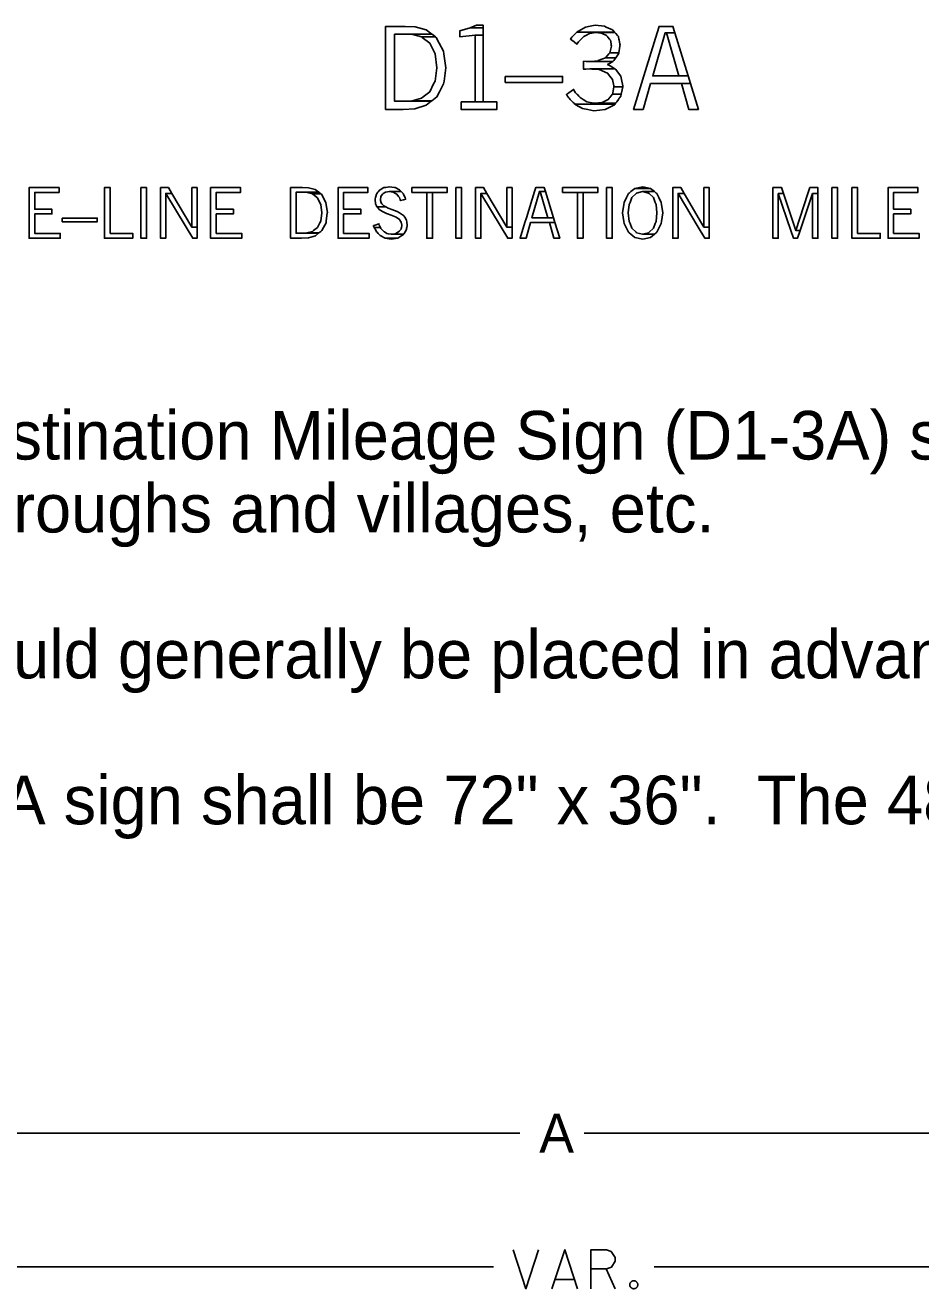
# Model space of a CAD drawing. Extents: x 0.011 to 0.188, y 0.004 to 0.261.
# Drawn here: x 0.0822 to 0.1286, y 0.1954 to 0.2609 of the extents above; entities that cross this region are included whole.
import ezdxf

# ---------------------------------------------------------------- set-up
doc = ezdxf.new("R2010")
doc.units = 0
doc.layers.add('1', color=7, linetype='Continuous')
doc.layers.add('3', color=7, linetype='Continuous')

msp = doc.modelspace()

# ---------------------------------------------------------------- linework, layer by layer
at = {"layer": '1'}
for points in [[(0.100861, 0.256562), (0.100861, 0.256526), (0.101776, 0.256526), (0.10237, 0.256562), (0.102964, 0.256741), (0.103229, 0.256947), (0.101328, 0.256947), (0.101328, 0.256972), (0.101328, 0.257102), (0.101328, 0.257171), (0.101328, 0.257439), (0.101328, 0.257841), (0.101328, 0.257985), (0.101328, 0.258672), (0.101328, 0.258675), (0.101328, 0.259396), (0.101328, 0.259539), (0.101328, 0.25995), (0.101328, 0.260253), (0.101328, 0.260283), (0.101328, 0.260403), (0.101328, 0.260422), (0.103257, 0.260422), (0.102956, 0.26065), (0.102393, 0.260797), (0.101881, 0.260822), (0.100861, 0.260822), (0.100861, 0.260797), (0.100861, 0.26065), (0.100861, 0.260422), (0.100861, 0.260403), (0.100861, 0.260283), (0.100861, 0.260253), (0.100861, 0.25995), (0.100861, 0.259539), (0.100861, 0.259396), (0.100861, 0.258675), (0.100861, 0.258672), (0.100861, 0.257985), (0.100861, 0.257841), (0.100861, 0.257439), (0.100861, 0.257171), (0.100861, 0.257102), (0.100861, 0.256972), (0.100861, 0.256947), (0.100861, 0.256741)], [(0.1047, 0.260379), (0.1047, 0.26029), (0.105496, 0.260379), (0.105922, 0.260379), (0.105922, 0.260588), (0.105922, 0.260753), (0.105244, 0.260753), (0.1047, 0.260588)], [(0.105575, 0.260884), (0.105244, 0.260753), (0.105922, 0.260753), (0.105922, 0.260884)], [(0.110984, 0.260653), (0.110775, 0.26053), (0.11272, 0.26053), (0.112616, 0.260653), (0.112298, 0.260794), (0.112206, 0.260836), (0.111724, 0.260884), (0.111723, 0.260884), (0.111456, 0.260836), (0.111226, 0.260794)], [(0.114117, 0.257862), (0.113706, 0.256526), (0.114206, 0.256526), (0.11459, 0.257862), (0.116661, 0.257862), (0.116538, 0.258261), (0.114704, 0.258261), (0.115347, 0.260499), (0.115849, 0.260499), (0.11575, 0.260822), (0.115028, 0.260822), (0.114929, 0.260499), (0.114239, 0.258261)], [(0.102266, 0.260403), (0.102716, 0.260283), (0.10344, 0.260283), (0.103282, 0.260403), (0.103257, 0.260422), (0.101775, 0.260422)], [(0.102727, 0.257102), (0.102228, 0.256972), (0.103261, 0.256972), (0.103429, 0.257102), (0.103518, 0.257171), (0.103658, 0.257439), (0.103868, 0.257841), (0.103888, 0.257985), (0.103979, 0.258672), (0.10398, 0.258675), (0.103877, 0.259396), (0.103857, 0.259539), (0.10364, 0.25995), (0.103481, 0.260253), (0.10344, 0.260283), (0.102716, 0.260283), (0.102756, 0.260253), (0.103148, 0.25995), (0.103351, 0.259539), (0.103422, 0.259396), (0.10351, 0.258675), (0.103511, 0.258672), (0.10342, 0.257985), (0.103349, 0.257841), (0.103151, 0.257439), (0.102813, 0.257171)], [(0.105496, 0.26029), (0.105496, 0.256911), (0.105922, 0.256911), (0.105922, 0.26029), (0.105922, 0.260379), (0.105496, 0.260379)], [(0.110635, 0.260018), (0.110777, 0.259912), (0.110855, 0.260018), (0.110945, 0.260111), (0.111, 0.260168), (0.1111, 0.260271), (0.111111, 0.260282), (0.11114, 0.260298), (0.111231, 0.260348), (0.11123, 0.260348), (0.111421, 0.260452), (0.111552, 0.260473), (0.111736, 0.260502), (0.112745, 0.260502), (0.11272, 0.26053), (0.110775, 0.26053), (0.110746, 0.260502), (0.110717, 0.260473), (0.110696, 0.260452), (0.110591, 0.260348), (0.11054, 0.260298), (0.110524, 0.260282), (0.110513, 0.260271), (0.110436, 0.260168), (0.110511, 0.260111)], [(0.112564, 0.259795), (0.112483, 0.259462), (0.112946, 0.259462), (0.113006, 0.259795), (0.113016, 0.259846), (0.113001, 0.259912), (0.112979, 0.260018), (0.112959, 0.260111), (0.112947, 0.260168), (0.112925, 0.260271), (0.112923, 0.260282), (0.11292, 0.260298), (0.112877, 0.260348), (0.112788, 0.260452), (0.11277, 0.260473), (0.112745, 0.260502), (0.111736, 0.260502), (0.112032, 0.260473), (0.112078, 0.260452), (0.112312, 0.260348), (0.112353, 0.260298), (0.112366, 0.260282), (0.112376, 0.260271), (0.112461, 0.260168), (0.112509, 0.260111), (0.112524, 0.260018), (0.112543, 0.259912), (0.112555, 0.259846)], [(0.115412, 0.260499), (0.116054, 0.258261), (0.116538, 0.258261), (0.115849, 0.260499)], [(0.11243, 0.259402), (0.112256, 0.259201), (0.112795, 0.259201), (0.112936, 0.259402), (0.112946, 0.259462), (0.112482, 0.259462)], [(0.11112, 0.25861), (0.11112, 0.258609), (0.111142, 0.25861), (0.111229, 0.258616), (0.11145, 0.258624), (0.112744, 0.258624), (0.112494, 0.258786), (0.112359, 0.258844), (0.11247, 0.258896), (0.112629, 0.259007), (0.111443, 0.259007), (0.111259, 0.259013), (0.11112, 0.259021), (0.11112, 0.259013), (0.11112, 0.259007), (0.11112, 0.258896), (0.11112, 0.258844), (0.11112, 0.258786), (0.11112, 0.258624), (0.11112, 0.258616)], [(0.111512, 0.259013), (0.111443, 0.259007), (0.112629, 0.259007), (0.112637, 0.259013), (0.112676, 0.25904), (0.11269, 0.25905), (0.112795, 0.259201), (0.112255, 0.259201), (0.111882, 0.25905), (0.111859, 0.25904)], [(0.112683, 0.257744), (0.112692, 0.2577), (0.113146, 0.2577), (0.113155, 0.257744), (0.113086, 0.258073), (0.113049, 0.258251), (0.112933, 0.258397), (0.112786, 0.258584), (0.112786, 0.258584), (0.112766, 0.258609), (0.112766, 0.25861), (0.112757, 0.258616), (0.112744, 0.258624), (0.11145, 0.258624), (0.111549, 0.258616), (0.111614, 0.25861), (0.11163, 0.258609), (0.111926, 0.258584), (0.112364, 0.258397), (0.112481, 0.258251), (0.112624, 0.258073)], [(0.10706, 0.258234), (0.10706, 0.257924), (0.110029, 0.257924), (0.110029, 0.258234)], [(0.110626, 0.256841), (0.11067, 0.256799), (0.11275, 0.256799), (0.112781, 0.256841), (0.111684, 0.256841), (0.111456, 0.256885), (0.111294, 0.256917), (0.111095, 0.257038), (0.110996, 0.257098), (0.110938, 0.257134), (0.110865, 0.257214), (0.11078, 0.257309), (0.11077, 0.25732), (0.110707, 0.25739), (0.110599, 0.257563), (0.110347, 0.25739), (0.110245, 0.25732), (0.11023, 0.257309), (0.110291, 0.257214), (0.110342, 0.257134), (0.110366, 0.257098), (0.110427, 0.257038), (0.110549, 0.256917), (0.110582, 0.256885)], [(0.112077, 0.256885), (0.111684, 0.256841), (0.112781, 0.256841), (0.112813, 0.256885), (0.112837, 0.256917), (0.112925, 0.257038), (0.112969, 0.257098), (0.112996, 0.257134), (0.112995, 0.257134), (0.113054, 0.257214), (0.113072, 0.257309), (0.113074, 0.25732), (0.112621, 0.25732), (0.112612, 0.257309), (0.112538, 0.257214), (0.112475, 0.257134), (0.112448, 0.257098), (0.1124, 0.257038), (0.112144, 0.256917)], [(0.112634, 0.25739), (0.112621, 0.25732), (0.113074, 0.25732), (0.113087, 0.25739), (0.113146, 0.2577), (0.112691, 0.2577)], [(0.116187, 0.257862), (0.116572, 0.256526), (0.117072, 0.256526), (0.116661, 0.257862)], [(0.102228, 0.256972), (0.101709, 0.256947), (0.103229, 0.256947), (0.103261, 0.256972)], [(0.104773, 0.256911), (0.104773, 0.256526), (0.106626, 0.256526), (0.106626, 0.256911)], [(0.111344, 0.256514), (0.111645, 0.256456), (0.112237, 0.256514), (0.11234, 0.256568), (0.112726, 0.256766), (0.11275, 0.256799), (0.110669, 0.256799), (0.110726, 0.256766), (0.111065, 0.256568)], [(0.082388, 0.2501), (0.082388, 0.249848), (0.083998, 0.249848), (0.083998, 0.2501), (0.082676, 0.2501), (0.082676, 0.251105), (0.083569, 0.251105), (0.083569, 0.251349), (0.082676, 0.251349), (0.082676, 0.252226), (0.083936, 0.252226), (0.083936, 0.252474), (0.082388, 0.252474), (0.082388, 0.252226), (0.082388, 0.251349), (0.082388, 0.251105)], [(0.08629, 0.2501), (0.08629, 0.249848), (0.08776, 0.249848), (0.08776, 0.2501), (0.086587, 0.2501), (0.086587, 0.252474), (0.08629, 0.252474)], [(0.088181, 0.252474), (0.088181, 0.249848), (0.088475, 0.249848), (0.088475, 0.252474)], [(0.089197, 0.250424), (0.089197, 0.249848), (0.08947, 0.249848), (0.08947, 0.250424), (0.08947, 0.252171), (0.089786, 0.252171), (0.089609, 0.252474), (0.089197, 0.252474), (0.089197, 0.252171)], [(0.090517, 0.250424), (0.090862, 0.249848), (0.091087, 0.249848), (0.091087, 0.250424), (0.090814, 0.250424), (0.089786, 0.252171), (0.08947, 0.252171)], [(0.090814, 0.252474), (0.090814, 0.250424), (0.091087, 0.250424), (0.091087, 0.252474)], [(0.091793, 0.2501), (0.091793, 0.249848), (0.093402, 0.249848), (0.093402, 0.2501), (0.092081, 0.2501), (0.092081, 0.251105), (0.092974, 0.251105), (0.092974, 0.251349), (0.092081, 0.251349), (0.092081, 0.252226), (0.093341, 0.252226), (0.093341, 0.252474), (0.091793, 0.252474), (0.091793, 0.252226), (0.091793, 0.251349), (0.091793, 0.251105)], [(0.095934, 0.24987), (0.095934, 0.249848), (0.096494, 0.249848), (0.096857, 0.24987), (0.09722, 0.249979), (0.097382, 0.250106), (0.09622, 0.250106), (0.09622, 0.250121), (0.09622, 0.2502), (0.09622, 0.250242), (0.09622, 0.250406), (0.09622, 0.250652), (0.09622, 0.25074), (0.09622, 0.25116), (0.09622, 0.251161), (0.09622, 0.251603), (0.09622, 0.25169), (0.09622, 0.251941), (0.09622, 0.252126), (0.09622, 0.252144), (0.09622, 0.252217), (0.09622, 0.252229), (0.097399, 0.252229), (0.097215, 0.252369), (0.096871, 0.252459), (0.096558, 0.252474), (0.095934, 0.252474), (0.095934, 0.252459), (0.095934, 0.252369), (0.095934, 0.252229), (0.095934, 0.252217), (0.095934, 0.252144), (0.095934, 0.252126), (0.095934, 0.251941), (0.095934, 0.25169), (0.095934, 0.251603), (0.095934, 0.251161), (0.095934, 0.25116), (0.095934, 0.25074), (0.095934, 0.250652), (0.095934, 0.250406), (0.095934, 0.250242), (0.095934, 0.2502), (0.095934, 0.250121), (0.095934, 0.250106), (0.095934, 0.249979)], [(0.096793, 0.252217), (0.097069, 0.252144), (0.097511, 0.252144), (0.097414, 0.252217), (0.097399, 0.252229), (0.096493, 0.252229)], [(0.097075, 0.2502), (0.09677, 0.250121), (0.097401, 0.250121), (0.097504, 0.2502), (0.097558, 0.250242), (0.097644, 0.250406), (0.097772, 0.250652), (0.097784, 0.25074), (0.09784, 0.25116), (0.097841, 0.251161), (0.097778, 0.251603), (0.097766, 0.25169), (0.097633, 0.251941), (0.097536, 0.252126), (0.097511, 0.252144), (0.097068, 0.252144), (0.097092, 0.252126), (0.097332, 0.251941), (0.097456, 0.25169), (0.097499, 0.251603), (0.097554, 0.251161), (0.097554, 0.25116), (0.097499, 0.25074), (0.097455, 0.250652), (0.097334, 0.250406), (0.097128, 0.250242)], [(0.098396, 0.2501), (0.098396, 0.249848), (0.100005, 0.249848), (0.100005, 0.2501), (0.098684, 0.2501), (0.098684, 0.251105), (0.099577, 0.251105), (0.099577, 0.251349), (0.098684, 0.251349), (0.098684, 0.252226), (0.099944, 0.252226), (0.099944, 0.252474), (0.098396, 0.252474), (0.098396, 0.252226), (0.098396, 0.251349), (0.098396, 0.251105)], [(0.100385, 0.251524), (0.100409, 0.251469), (0.100866, 0.251469), (0.10076, 0.251524), (0.100662, 0.251639), (0.100626, 0.251682), (0.100601, 0.251798), (0.100591, 0.251844), (0.100596, 0.251875), (0.1006, 0.251898), (0.100609, 0.251954), (0.10061, 0.25196), (0.10062, 0.252013), (0.100696, 0.252129), (0.100709, 0.252149), (0.100722, 0.252157), (0.100739, 0.252168), (0.10086, 0.252242), (0.100863, 0.252243), (0.10105, 0.252273), (0.101665, 0.252273), (0.101601, 0.252341), (0.101579, 0.252364), (0.101358, 0.252469), (0.101323, 0.252486), (0.101044, 0.252516), (0.101043, 0.252516), (0.100871, 0.252486), (0.100772, 0.252469), (0.100583, 0.252364), (0.100541, 0.252341), (0.100486, 0.252273), (0.100462, 0.252243), (0.10046, 0.252242), (0.1004, 0.252168), (0.100391, 0.252157), (0.100388, 0.252149), (0.100383, 0.252129), (0.100348, 0.252013), (0.100333, 0.25196), (0.100331, 0.251954), (0.100315, 0.251898), (0.100316, 0.251875), (0.100318, 0.251844), (0.100321, 0.251798), (0.100329, 0.251682), (0.100332, 0.251639)], [(0.101622, 0.251844), (0.101639, 0.251798), (0.101794, 0.251844), (0.101901, 0.251875), (0.101893, 0.251898), (0.101876, 0.251954), (0.101874, 0.25196), (0.101846, 0.252013), (0.101785, 0.252129), (0.101774, 0.252149), (0.10177, 0.252157), (0.101765, 0.252168), (0.101694, 0.252242), (0.101693, 0.252243), (0.101665, 0.252273), (0.10105, 0.252273), (0.101239, 0.252243), (0.10125, 0.252242), (0.101381, 0.252168), (0.1014, 0.252157), (0.101414, 0.252149), (0.10145, 0.252129), (0.101535, 0.252013), (0.101575, 0.25196), (0.10158, 0.251954), (0.101601, 0.251898), (0.10161, 0.251875)], [(0.102227, 0.252474), (0.102227, 0.252222), (0.104056, 0.252222), (0.104056, 0.252474)], [(0.102993, 0.252222), (0.102993, 0.249848), (0.10329, 0.249848), (0.10329, 0.252222)], [(0.104507, 0.252474), (0.104507, 0.249848), (0.104801, 0.249848), (0.104801, 0.252474)], [(0.105524, 0.250424), (0.105524, 0.249848), (0.105797, 0.249848), (0.105797, 0.250424), (0.105797, 0.252171), (0.106113, 0.252171), (0.105936, 0.252474), (0.105524, 0.252474), (0.105524, 0.252171)], [(0.106844, 0.250424), (0.107189, 0.249848), (0.107414, 0.249848), (0.107414, 0.250424), (0.107141, 0.250424), (0.106113, 0.252171), (0.105797, 0.252171)], [(0.107141, 0.252474), (0.107141, 0.250424), (0.107414, 0.250424), (0.107414, 0.252474)], [(0.108081, 0.250665), (0.10783, 0.249848), (0.108136, 0.249848), (0.10837, 0.250665), (0.109636, 0.250665), (0.109561, 0.250909), (0.10844, 0.250909), (0.108833, 0.252276), (0.10914, 0.252276), (0.109079, 0.252474), (0.108638, 0.252474), (0.108577, 0.252276), (0.108156, 0.250909)], [(0.108872, 0.252276), (0.109265, 0.250909), (0.109561, 0.250909), (0.10914, 0.252276)], [(0.110032, 0.252474), (0.110032, 0.252222), (0.111861, 0.252222), (0.111861, 0.252474)], [(0.110797, 0.252222), (0.110797, 0.249848), (0.111094, 0.249848), (0.111094, 0.252222)], [(0.112312, 0.252474), (0.112312, 0.249848), (0.112606, 0.249848), (0.112606, 0.252474)], [(0.113773, 0.24989), (0.114181, 0.249806), (0.114589, 0.24989), (0.114797, 0.250058), (0.11418, 0.250058), (0.11387, 0.250129), (0.113838, 0.250159), (0.113626, 0.250362), (0.113527, 0.250613), (0.113484, 0.250724), (0.113437, 0.251161), (0.113484, 0.251597), (0.113527, 0.251708), (0.113626, 0.25196), (0.113838, 0.252162), (0.11387, 0.252192), (0.11418, 0.252264), (0.114797, 0.252264), (0.114589, 0.252432), (0.113772, 0.252432), (0.113565, 0.252264), (0.113476, 0.252192), (0.113439, 0.252162), (0.113339, 0.25196), (0.113215, 0.251708), (0.1132, 0.251597), (0.113143, 0.251161), (0.1132, 0.250724), (0.113215, 0.250613), (0.113339, 0.250362), (0.113439, 0.250159), (0.113476, 0.250129), (0.113565, 0.250058)], [(0.114181, 0.252516), (0.113773, 0.252432), (0.114589, 0.252432)], [(0.11449, 0.250129), (0.11418, 0.250058), (0.114797, 0.250058), (0.114885, 0.250129), (0.114885, 0.250129), (0.114923, 0.250159), (0.115023, 0.250362), (0.115147, 0.250613), (0.115161, 0.250724), (0.115218, 0.251161), (0.115161, 0.251597), (0.115147, 0.251708), (0.115023, 0.25196), (0.114923, 0.252162), (0.114885, 0.252192), (0.114885, 0.252192), (0.114797, 0.252264), (0.11418, 0.252264), (0.11449, 0.252192), (0.114522, 0.252162), (0.114734, 0.25196), (0.114832, 0.251708), (0.114876, 0.251597), (0.114923, 0.251161), (0.114876, 0.250724), (0.114832, 0.250613), (0.114734, 0.250362), (0.114522, 0.250159)], [(0.115739, 0.250424), (0.115739, 0.249848), (0.116012, 0.249848), (0.116012, 0.250424), (0.116012, 0.252171), (0.116329, 0.252171), (0.116151, 0.252474), (0.115739, 0.252474), (0.115739, 0.252171)], [(0.117059, 0.250424), (0.117404, 0.249848), (0.117629, 0.249848), (0.117629, 0.250424), (0.117356, 0.250424), (0.116329, 0.252171), (0.116012, 0.252171)], [(0.117356, 0.252474), (0.117356, 0.250424), (0.117629, 0.250424), (0.117629, 0.252474)], [(0.120931, 0.250255), (0.120931, 0.249848), (0.121211, 0.249848), (0.121211, 0.250255), (0.121211, 0.252159), (0.12148, 0.252159), (0.121376, 0.252474), (0.120931, 0.252474), (0.120931, 0.252159)], [(0.12186, 0.250255), (0.121999, 0.249848), (0.122198, 0.249848), (0.122336, 0.250255), (0.12211, 0.250255), (0.12148, 0.252159), (0.121211, 0.252159)], [(0.122743, 0.252159), (0.12211, 0.250255), (0.122336, 0.250255), (0.122987, 0.252159), (0.123266, 0.252159), (0.123266, 0.252474), (0.122848, 0.252474)], [(0.122987, 0.250255), (0.122987, 0.249848), (0.123266, 0.249848), (0.123266, 0.250255), (0.123266, 0.252159), (0.122987, 0.252159)], [(0.123989, 0.252474), (0.123989, 0.249848), (0.124283, 0.249848), (0.124283, 0.252474)], [(0.125022, 0.2501), (0.125022, 0.249848), (0.126492, 0.249848), (0.126492, 0.2501), (0.125319, 0.2501), (0.125319, 0.252474), (0.125022, 0.252474)], [(0.126895, 0.2501), (0.126895, 0.249848), (0.128505, 0.249848), (0.128505, 0.2501), (0.127184, 0.2501), (0.127184, 0.251105), (0.128077, 0.251105), (0.128077, 0.251349), (0.127184, 0.251349), (0.127184, 0.252226), (0.128444, 0.252226), (0.128444, 0.252474), (0.126895, 0.252474), (0.126895, 0.252226), (0.126895, 0.251349), (0.126895, 0.251105)], [(0.101361, 0.250084), (0.10115, 0.250056), (0.101796, 0.250056), (0.101815, 0.250084), (0.101822, 0.250095), (0.101873, 0.250172), (0.101884, 0.250188), (0.101883, 0.250188), (0.101897, 0.250208), (0.101933, 0.250262), (0.101943, 0.250322), (0.101949, 0.250358), (0.101957, 0.250402), (0.101973, 0.250496), (0.101975, 0.250507), (0.101976, 0.250513), (0.10198, 0.250531), (0.101956, 0.250684), (0.101941, 0.250789), (0.10192, 0.250825), (0.101851, 0.250938), (0.101805, 0.251014), (0.101779, 0.251032), (0.101636, 0.251136), (0.101588, 0.251172), (0.101451, 0.25123), (0.10132, 0.251287), (0.101187, 0.251335), (0.100987, 0.251407), (0.100866, 0.251469), (0.100409, 0.251469), (0.100467, 0.251407), (0.100534, 0.251335), (0.100609, 0.251287), (0.100698, 0.25123), (0.100832, 0.251172), (0.100913, 0.251136), (0.101197, 0.251032), (0.101239, 0.251014), (0.101413, 0.250938), (0.101582, 0.250825), (0.101605, 0.250789), (0.101672, 0.250684), (0.101695, 0.250531), (0.101698, 0.250513), (0.101697, 0.250507), (0.101694, 0.250496), (0.101675, 0.250402), (0.101666, 0.250358), (0.101659, 0.250322), (0.101609, 0.250262), (0.101565, 0.250208), (0.101549, 0.250188), (0.101536, 0.250172), (0.101383, 0.250095)], [(0.084106, 0.250892), (0.084106, 0.250703), (0.085921, 0.250703), (0.085921, 0.250892)], [(0.09677, 0.250121), (0.096453, 0.250106), (0.097382, 0.250106), (0.097401, 0.250121)], [(0.100241, 0.250496), (0.100275, 0.250402), (0.100592, 0.250402), (0.100544, 0.250496), (0.10054, 0.250507), (0.100538, 0.250513), (0.100533, 0.250531), (0.100532, 0.250531), (0.100512, 0.250595), (0.100512, 0.250595), (0.100313, 0.250531), (0.100255, 0.250513), (0.100237, 0.250507)], [(0.10058, 0.249982), (0.100833, 0.249853), (0.101489, 0.249853), (0.101706, 0.249982), (0.101775, 0.250022), (0.101796, 0.250056), (0.10115, 0.250056), (0.100994, 0.250084), (0.100993, 0.250084), (0.100932, 0.250095), (0.100806, 0.250172), (0.10078, 0.250188), (0.100747, 0.250208), (0.1007, 0.250262), (0.100646, 0.250322), (0.100646, 0.250322), (0.100614, 0.250358), (0.100592, 0.250402), (0.100275, 0.250402), (0.100297, 0.250358), (0.100316, 0.250322), (0.100347, 0.250262), (0.100375, 0.250208), (0.100386, 0.250188), (0.100401, 0.250172), (0.100474, 0.250095), (0.100484, 0.250084), (0.10051, 0.250056), (0.100542, 0.250022)], [(0.109346, 0.250665), (0.109581, 0.249848), (0.109887, 0.249848), (0.109636, 0.250665)], [(0.100838, 0.249853), (0.101143, 0.249806), (0.101487, 0.249853), (0.101489, 0.249853), (0.100832, 0.249853)]]:
    msp.add_lwpolyline(points, close=True, dxfattribs=at)
at = {"layer": '3'}
for p, q in [((0.107815, 0.20348), (0.049001, 0.20348)), ((0.111148, 0.20348), (0.169961, 0.20348)), ((0.106457, 0.19655), (0.077855, 0.19655)), ((0.114773, 0.19655), (0.143375, 0.19655))]:
    msp.add_line(p, q, dxfattribs=at)
for points in [[(0.107465, 0.197433), (0.108132, 0.195416), (0.108783, 0.197433)], [(0.109482, 0.195416), (0.110148, 0.197433), (0.110799, 0.195416)], [(0.111498, 0.195416), (0.111498, 0.197433), (0.112308, 0.197433), (0.112546, 0.197353), (0.112752, 0.197036), (0.112752, 0.196845), (0.112562, 0.196528), (0.112308, 0.196448), (0.111498, 0.196448)], [(0.112752, 0.195416), (0.112292, 0.196448)], [(0.10964, 0.195893), (0.110641, 0.195893)], [(0.113927, 0.195623), (0.113926, 0.195644), (0.113922, 0.195666), (0.113917, 0.195686), (0.113909, 0.195707), (0.113899, 0.195726), (0.113887, 0.195744), (0.113874, 0.195761), (0.113859, 0.195776), (0.113842, 0.19579), (0.113824, 0.195801), (0.113804, 0.195811), (0.113784, 0.195819), (0.113763, 0.195825), (0.113742, 0.195828), (0.11372, 0.195829), (0.113699, 0.195828), (0.113678, 0.195825), (0.113657, 0.195819), (0.113637, 0.195811), (0.113617, 0.195801), (0.113599, 0.19579), (0.113582, 0.195776), (0.113567, 0.195761), (0.113554, 0.195744), (0.113542, 0.195726), (0.113532, 0.195707), (0.113524, 0.195686), (0.113519, 0.195666), (0.113515, 0.195644), (0.113514, 0.195623), (0.113515, 0.195601), (0.113519, 0.19558), (0.113524, 0.195559), (0.113532, 0.195539), (0.113542, 0.19552), (0.113554, 0.195501), (0.113567, 0.195485), (0.113582, 0.195469), (0.113599, 0.195456), (0.113617, 0.195444), (0.113637, 0.195434), (0.113657, 0.195427), (0.113678, 0.195421), (0.113699, 0.195417), (0.11372, 0.195416), (0.113742, 0.195417), (0.113763, 0.195421), (0.113784, 0.195427), (0.113804, 0.195434), (0.113824, 0.195444), (0.113842, 0.195456), (0.113859, 0.195469), (0.113874, 0.195485), (0.113887, 0.195501), (0.113899, 0.19552), (0.113909, 0.195539), (0.113917, 0.195559), (0.113922, 0.19558), (0.113926, 0.195601), (0.113927, 0.195623)]]:
    msp.add_lwpolyline(points, dxfattribs=at)

# ---------------------------------------------------------------- texts
for s, height, p in [('   (a) Justification.  The Triple-Line Destination Mileage Sign (D1-3A) shall be authorized for use to indicate', 0.002519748, (0.025187, 0.238382)), ('the direction and distance to cities, boroughs and villages, etc.', 0.00251975, (0.025187, 0.234602)), ('   (b) Placement.  The D1-3A sign should generally be placed in advance of an intersection.', 0.00251975, (0.025187, 0.227042)), ('   (c) Size.  The standard size of D1-3A sign shall be 72" x 36".  The 48" x 24" size may be used on', 0.00251975, (0.025187, 0.219482)), ('A', 0.002016, (0.108823, 0.202472))]:
    msp.add_text(s, height=height, dxfattribs=at).set_placement(p)

doc.saveas('drawing.dxf')
